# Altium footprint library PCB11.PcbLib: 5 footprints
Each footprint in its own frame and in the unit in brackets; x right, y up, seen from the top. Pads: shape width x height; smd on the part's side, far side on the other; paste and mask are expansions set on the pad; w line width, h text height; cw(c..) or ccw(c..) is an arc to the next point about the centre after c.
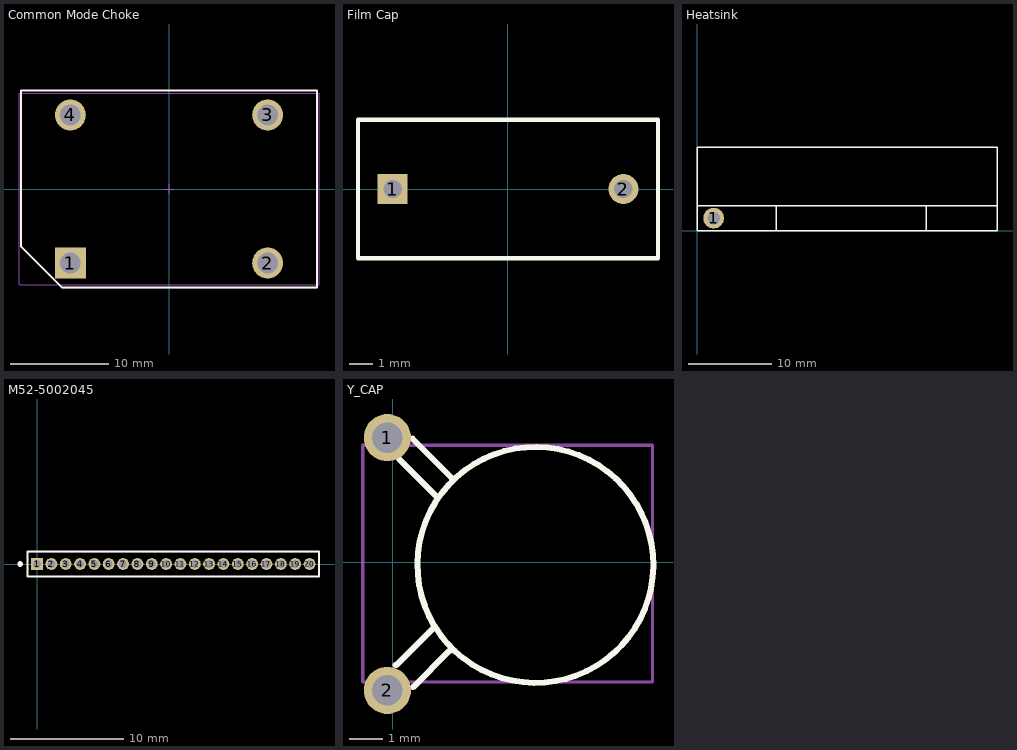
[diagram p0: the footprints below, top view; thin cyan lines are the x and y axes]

## Common Mode Choke [mm]
height 30
pads (4):
  rect 3.15x3.15 hole 2.1: 1(-10,-7.5)
  round 3.15 hole 2.1: 2(10,-7.5) 3(10,7.5) 4(-10,7.5)
Top Overlay:
  lines w0.2: -15,-5.8 -10.8,-10 15,-10 15,10 -15,10 -15,-5.8
Mechanical 13:
  lines w0.1: -15,-5.8 -15,10 15,10 15,-10 -10.8,-10 -15,-5.8
Mechanical 15:
  lines w0.05: -0.5,0 0.5,0 ; 0,-0.5 0,0.5 ; -15.2,-9.7 15.2,-9.7 15.2,9.7 -15.2,9.7 -15.2,-9.7
3D body "7448042001_30x19x30.stp": height 25.72, standoff -4.75, extent -13.75,-9 13.75,9

## Film Cap [mm]
height 14.2
pads (2):
  rect 1.3x1.3 hole 0.8: 1(-5,0)
  round 1.3 hole 0.8: 2(5,0)
Top Overlay:
  lines w0.178: -6.5,-3 1,-3 6.5,-3 6.5,0 6.5,3 1,3 -6.5,3 -6.5,0 -6.5,-3
Mechanical 5:
  lines w0.127: -6.5,-3 -6.5,0 -6.5,3 1,3 6.5,3 6.5,0 6.5,-3 1,-3 -6.5,-3
  text ".Designator" at -1.524,-0.508 h1.02
3D body: height 14.2, standoff 0, extent -6.499,-2.999 6.499,2.999

## Heatsink [mm]
height 31
pads (1):
  round 2.5 hole 1.5: 1(2,1.5)
Top Overlay:
  lines w0.178: 0,3 36,3 ; 9.5,0 9.5,3 ; 27.5,0 27.5,3 ; 0,0 36,0 36,10 0,10 0,0
3D body: height 31.3, standoff 26, extent 0,0 36,10
3D body: height 26, standoff 2.5, extent 0,0 36,3

## M52-5002045 [mm] "CONN RCPT 20POS 0.05 GOLD PCB"
height 4.089
pads (20):
  rect 1.05x1.05 hole 0.7: 1(0,0)
  round 1.05 hole 0.7: 2(1.27,0) 3(2.54,0) 4(3.81,0) 5(5.08,0) 6(6.35,0) 7(7.62,0) 8(8.89,0) 9(10.16,0) 10(11.43,0) 11(12.7,0) 12(13.97,0) 13(15.24,0) 14(16.51,0) 15(17.78,0) 16(19.05,0) 17(20.32,0) 18(21.59,0) 19(22.86,0) 20(24.13,0)
Top Overlay:
  circle w0.3: c-1.497,0 r0.1
  lines w0.2: -0.84,-1.1 -0.84,1.1 24.97,1.1 24.97,-1.1 -0.84,-1.1
Mechanical 5:
  region: -0.508,0.508 0.254,0.508 0.254,-0.508 -0.508,-0.508
  lines w0.1: -0.84,-1.1 -0.84,1.1 24.97,1.1 24.97,-1.1 -0.84,-1.1
  text ".Designator" at 0.559,-0.533 h1.02
3D body: height 4.1, standoff 4.1, extent -0.298,-0.299 0.3,0.299
3D body: height 4.1, standoff 0, extent -0.84,-1.1 24.975,1.1

## Y_CAP [mm]
pads (2):
  round 1.4 hole 0.9: 1(-0.165,3.701) 2(-0.165,-3.799)
Top Overlay:
  lines w0.178: 0.075,-3.05 0.1,-3.05 1.2,-1.95 ; 0.175,3.075 1.3,1.95 ; 0.575,3.675 1.75,2.5 1.75,2.45 ; 1.675,-2.625 0.6,-3.7 ; 7.725,-0.125 cw(c4.225,-0.075) 7.725,-0.1 ; 0.6,-3.7 0.6,-3.7
Mechanical 5:
  lines w0.1: -0.9,3.45 -0.9,-3.549 7.7,-3.549 7.7,3.45 ; -0.9,3.475 7.7,3.475
  text ".Designator" at -0.673,1.475 h1.02
3D body: height 2.5, standoff -4, extent -0.472,3.401 0.125,4
3D body: height 5, standoff 0, extent 0.725,-3.497 7.725,3.497
3D body: height 2.5, standoff -4, extent -0.472,-4.099 0.125,-3.5
3D body: height 2.8, standoff 2.2, extent -0.472,1.455 2.072,4
3D body: height 2.8, standoff 2.2, extent -0.475,3.402 0.125,3.998
3D body: height 2.8, standoff 2.2, extent -0.472,-4.1 2.072,-1.555
3D body: height 2.8, standoff 2.2, extent -0.472,-4.099 0.128,-3.504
